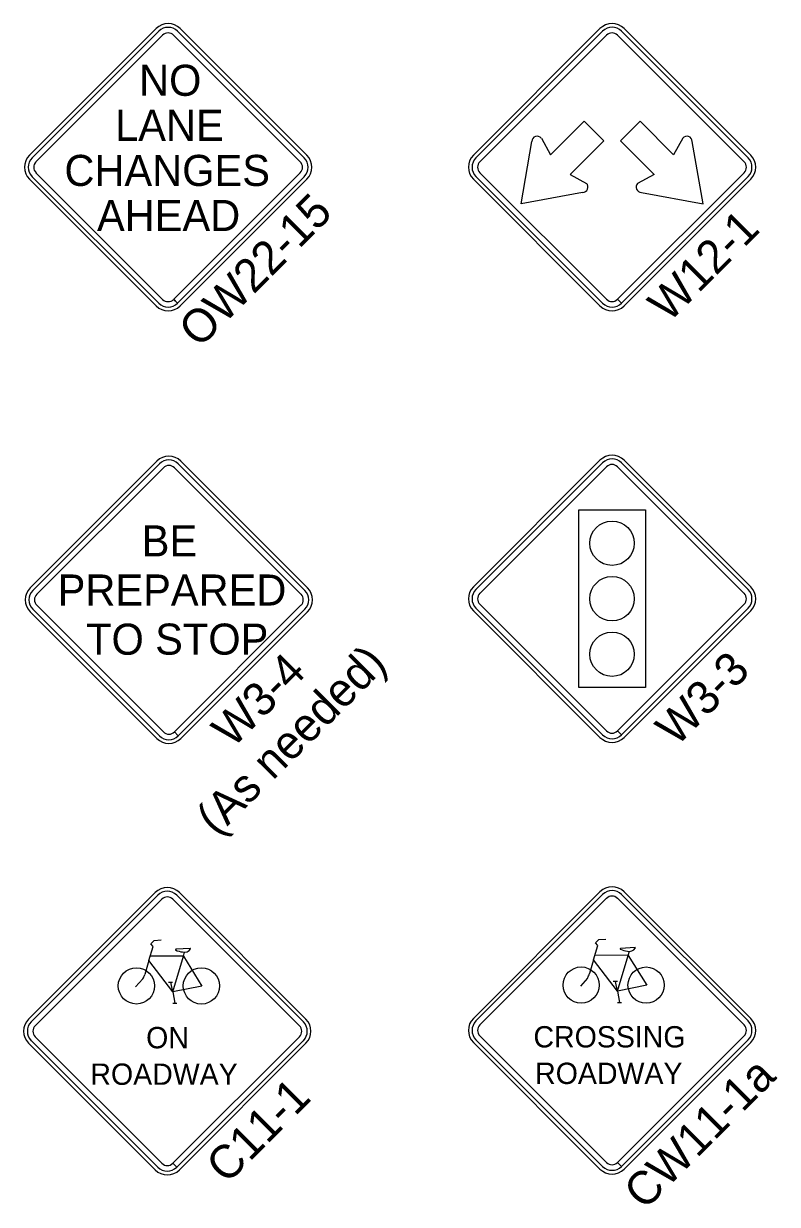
# Model space of a CAD drawing. Extents: x 1458 to 4498, y 17709 to 24109.
# Drawn here: x 3714 to 4053, y 22534 to 23066 of the extents above; entities that cross this region are included whole.
import ezdxf

# ---------------------------------------------------------------- set-up
doc = ezdxf.new("R2010")
doc.units = 0
doc.layers.add('P_TRAF_TCP_General', color=7, linetype='Continuous')

msp = doc.modelspace()

# ---------------------------------------------------------------- linework, layer by layer
at = {"layer": 'P_TRAF_TCP_General'}
for p, q in [((3773.42, 23063.84), (3716.41, 23006.84)), ((3774.6, 23062.66), (3717.6, 23005.65)), ((3840.09, 23005.65), (3783.09, 23062.66)), ((3841.27, 23006.84), (3784.27, 23063.84)), ((3973.24, 23063.86), (3916.24, 23006.85)), ((3974.43, 23062.67), (3917.42, 23005.67)), ((4039.91, 23005.67), (3982.91, 23062.67)), ((4041.1, 23006.85), (3984.09, 23063.86)), ((3719.36, 23003.89), (3776.37, 23060.89)), ((3781.32, 23060.89), (3838.32, 23003.89)), ((3919.19, 23003.9), (3976.19, 23060.9)), ((3981.14, 23060.9), (4038.15, 23003.9)), ((3950.95, 23006.99), (3966.07, 23022.12)), ((3966.07, 23022.13), (3974.9, 23013.29)), ((3991.27, 23022.13), (3982.43, 23013.29)), ((4006.39, 23006.99), (3991.26, 23022.12)), ((3946.84, 23014.48), (3950.95, 23006.99)), ((3974.9, 23013.3), (3959.77, 22998.17)), ((3982.44, 23013.3), (3997.56, 22998.17)), ((4010.5, 23014.48), (4006.39, 23006.99)), ((3937.71, 22984.93), (3942.58, 23013.03)), ((4019.62, 22984.93), (4014.76, 23013.03)), ((3776.37, 22941.93), (3719.36, 22998.94)), ((3838.32, 22998.94), (3781.34, 22941.95)), ((3976.19, 22941.95), (3919.19, 22998.95)), ((3976.19, 22941.95), (3919.19, 22998.95)), ((3959.77, 22998.17), (3967.14, 22994.16)), ((4038.15, 22998.95), (3981.16, 22941.96)), ((3997.56, 22998.17), (3990.2, 22994.16)), ((3716.41, 22995.99), (3773.42, 22938.98)), ((3717.6, 22997.17), (3774.6, 22940.17)), ((3783.1, 22940.18), (3840.09, 22997.17)), ((3784.27, 22938.98), (3841.27, 22995.99)), ((3916.24, 22996), (3973.24, 22939)), ((3917.42, 22997.18), (3974.43, 22940.18)), ((3917.42, 22997.18), (3974.43, 22940.18)), ((3982.93, 22940.2), (4039.91, 22997.18)), ((3984.09, 22939), (4041.1, 22996)), ((3965.44, 22990.12), (3937.71, 22984.93)), ((3991.89, 22990.12), (4019.62, 22984.93)), ((3783.09, 22940.17), (3781.32, 22941.93)), ((3783.09, 22940.17), (3781.32, 22941.93)), ((3781.34, 22941.95), (3783.1, 22940.18)), ((3781.34, 22941.95), (3783.1, 22940.18)), ((3982.91, 22940.18), (3981.14, 22941.95)), ((3982.91, 22940.18), (3981.14, 22941.95)), ((3981.16, 22941.96), (3982.93, 22940.2)), ((3773.75, 22869.06), (3716.74, 22812.06)), ((3774.93, 22867.88), (3717.93, 22810.87)), ((3774.93, 22867.88), (3717.93, 22810.87)), ((3774.93, 22867.88), (3717.93, 22810.87)), ((3719.69, 22809.11), (3776.7, 22866.11)), ((3719.69, 22809.11), (3776.7, 22866.11)), ((3781.65, 22866.11), (3838.65, 22809.11)), ((3781.65, 22866.11), (3838.65, 22809.11)), ((3840.42, 22810.87), (3783.41, 22867.88)), ((3840.42, 22810.87), (3783.41, 22867.88)), ((3840.42, 22810.87), (3783.41, 22867.88)), ((3841.6, 22812.06), (3784.6, 22869.06)), ((3973.24, 22869.5), (3916.24, 22812.5)), ((3974.43, 22868.32), (3917.42, 22811.31)), ((3919.19, 22809.54), (3976.19, 22866.55)), ((3981.14, 22866.55), (4038.15, 22809.54)), ((4039.91, 22811.31), (3982.91, 22868.32)), ((4041.1, 22812.5), (3984.09, 22869.5)), ((3716.74, 22801.21), (3773.75, 22744.2)), ((3717.93, 22802.39), (3774.93, 22745.39)), ((3717.93, 22802.39), (3774.93, 22745.39)), ((3717.93, 22802.39), (3774.93, 22745.39)), ((3776.7, 22747.15), (3719.69, 22804.16)), ((3776.7, 22747.15), (3719.69, 22804.16)), ((3838.65, 22804.16), (3781.66, 22747.17)), ((3838.65, 22804.16), (3781.66, 22747.17)), ((3783.41, 22745.39), (3840.42, 22802.39)), ((3783.43, 22745.4), (3840.42, 22802.39)), ((3783.43, 22745.4), (3840.42, 22802.39)), ((3784.6, 22744.2), (3841.6, 22801.21)), ((3916.24, 22801.65), (3973.24, 22744.64)), ((3917.42, 22802.83), (3974.43, 22745.82)), ((3976.19, 22747.59), (3919.19, 22804.6)), ((4038.15, 22804.6), (3981.16, 22747.61)), ((3982.93, 22745.84), (4039.91, 22802.83)), ((3984.09, 22744.64), (4041.1, 22801.65)), ((3982.91, 22745.82), (3981.14, 22747.59)), ((3982.91, 22745.82), (3981.14, 22747.59)), ((3981.16, 22747.61), (3982.93, 22745.84)), ((3981.16, 22747.61), (3982.93, 22745.84)), ((3783.41, 22745.39), (3781.65, 22747.15)), ((3783.41, 22745.39), (3781.65, 22747.15)), ((3781.66, 22747.17), (3783.43, 22745.4)), ((3781.66, 22747.17), (3783.43, 22745.4)), ((3773.04, 22674.77), (3716.04, 22617.77)), ((3774.23, 22673.59), (3717.22, 22616.58)), ((3839.71, 22616.58), (3782.71, 22673.59)), ((3840.9, 22617.77), (3783.89, 22674.77)), ((3973.24, 22675.15), (3916.24, 22618.14)), ((3974.43, 22673.96), (3917.42, 22616.96)), ((4039.91, 22616.96), (3982.91, 22673.96)), ((4041.1, 22618.14), (3984.09, 22675.15)), ((3718.99, 22614.81), (3775.99, 22671.82)), ((3780.94, 22671.82), (3837.95, 22614.81)), ((3919.19, 22615.19), (3976.19, 22672.2)), ((3981.14, 22672.2), (4038.15, 22615.19)), ((3771.06, 22651.77), (3772.49, 22653.25)), ((3771.06, 22651.77), (3772.49, 22653.25)), ((3772.08, 22650.55), (3771.06, 22651.77)), ((3772.08, 22650.55), (3771.06, 22651.77)), ((3772.49, 22653.25), (3775.72, 22653.45)), ((3772.49, 22653.25), (3775.72, 22653.45)), ((3971.26, 22652.15), (3972.69, 22653.63)), ((3971.26, 22652.15), (3972.69, 22653.63)), ((3972.28, 22650.93), (3971.26, 22652.15)), ((3972.28, 22650.93), (3971.26, 22652.15)), ((3972.69, 22653.63), (3975.92, 22653.83)), ((3972.69, 22653.63), (3975.92, 22653.83)), ((3770.1, 22644.15), (3772.08, 22650.55)), ((3770.1, 22644.15), (3772.08, 22650.55)), ((3788.84, 22649.62), (3782.28, 22649.25)), ((3788.84, 22649.62), (3782.28, 22649.25)), ((3785.76, 22646.08), (3786.26, 22647.98)), ((3785.76, 22646.08), (3786.26, 22647.98)), ((3970.3, 22644.53), (3972.28, 22650.93)), ((3970.3, 22644.53), (3972.28, 22650.93)), ((3985.96, 22646.45), (3970.89, 22646.53)), ((3981.09, 22630.43), (3985.96, 22646.45)), ((3981.09, 22630.43), (3985.96, 22646.45)), ((3989.04, 22650), (3982.48, 22649.62)), ((3989.04, 22650), (3982.48, 22649.62)), ((3985.96, 22646.45), (3986.46, 22648.35)), ((3985.96, 22646.45), (3986.46, 22648.35)), ((3985.96, 22646.45), (3994.28, 22633.05)), ((3985.96, 22646.45), (3994.28, 22633.05)), ((3770.1, 22644.15), (3768.37, 22637.94)), ((3770.1, 22644.15), (3768.37, 22637.94)), ((3780.89, 22630.06), (3770.1, 22644.15)), ((3780.89, 22630.06), (3770.1, 22644.15)), ((3785.76, 22646.08), (3770.69, 22646.15)), ((3780.89, 22630.06), (3785.76, 22646.08)), ((3780.89, 22630.06), (3785.76, 22646.08)), ((3785.76, 22646.08), (3794.08, 22632.68)), ((3785.76, 22646.08), (3794.08, 22632.68)), ((3970.3, 22644.53), (3968.57, 22638.31)), ((3970.3, 22644.53), (3968.57, 22638.31)), ((3981.09, 22630.43), (3970.3, 22644.53)), ((3981.09, 22630.43), (3970.3, 22644.53)), ((3767.46, 22635.89), (3764.2, 22632.33)), ((3767.46, 22635.89), (3764.2, 22632.33)), ((3967.66, 22636.27), (3964.4, 22632.71)), ((3967.66, 22636.27), (3964.4, 22632.71)), ((3779, 22634.49), (3780.88, 22634.49)), ((3779, 22634.49), (3780.88, 22634.49)), ((3780.89, 22630.06), (3780.03, 22634.42)), ((3794.08, 22632.68), (3780.89, 22630.06)), ((3794.08, 22632.68), (3780.89, 22630.06)), ((3979.2, 22634.87), (3981.08, 22634.87)), ((3979.2, 22634.87), (3981.08, 22634.87)), ((3981.09, 22630.43), (3980.23, 22634.8)), ((3994.28, 22633.05), (3981.09, 22630.43)), ((3994.28, 22633.05), (3981.09, 22630.43)), ((3780.89, 22630.06), (3781.86, 22624.92)), ((3780.89, 22630.06), (3781.86, 22624.92)), ((3981.09, 22630.43), (3982.07, 22625.29)), ((3981.09, 22630.43), (3982.07, 22625.29)), ((3981.12, 22625.33), (3982.99, 22625.33)), ((3981.12, 22625.33), (3982.99, 22625.33)), ((3780.92, 22624.96), (3782.79, 22624.96)), ((3780.92, 22624.96), (3782.79, 22624.96)), ((3775.99, 22552.86), (3718.99, 22609.87)), ((3837.95, 22609.87), (3780.96, 22552.88)), ((3976.19, 22553.24), (3919.19, 22610.24)), ((4038.15, 22610.24), (3981.16, 22553.25)), ((3716.04, 22606.92), (3773.04, 22549.91)), ((3717.22, 22608.1), (3774.23, 22551.09)), ((3782.73, 22551.11), (3839.71, 22608.1)), ((3783.89, 22549.91), (3840.9, 22606.92)), ((3916.24, 22607.29), (3973.24, 22550.29)), ((3917.42, 22608.48), (3974.43, 22551.47)), ((3982.93, 22551.49), (4039.91, 22608.48)), ((3984.09, 22550.29), (4041.1, 22607.29)), ((3782.71, 22551.09), (3780.94, 22552.86)), ((3782.71, 22551.09), (3780.94, 22552.86)), ((3780.96, 22552.88), (3782.73, 22551.11)), ((3780.96, 22552.88), (3782.73, 22551.11)), ((3982.91, 22551.47), (3981.14, 22553.24)), ((3982.91, 22551.47), (3981.14, 22553.24)), ((3981.16, 22553.25), (3982.93, 22551.49)), ((3981.16, 22553.25), (3982.93, 22551.49))]:
    msp.add_line(p, q, dxfattribs=at)
msp.add_lwpolyline([(3963.68, 22847.1), (3993.67, 22847.1), (3993.67, 22767.13), (3963.68, 22767.13)], close=True, dxfattribs=at)
for centre, radius in [((3978.68, 22832.11), 10), ((3978.68, 22807.12), 10), ((3978.68, 22782.13), 10), ((3964.76, 22633.14), 8.16), ((3994.01, 22633.12), 8.16), ((3764.56, 22632.76), 8.16), ((3793.81, 22632.75), 8.16)]:
    msp.add_circle(centre, radius, dxfattribs=at)
for centre, radius, start, end in [((3778.84, 23058.42), 7.67, 45, 135), ((3778.84, 23058.42), 6, 45, 135), ((3778.84, 23058.42), 3.5, 45, 135), ((3978.67, 23058.43), 7.67, 45, 135), ((3978.67, 23058.43), 6, 45, 135), ((3978.67, 23058.43), 3.5, 45, 135), ((3944.95, 23013.03), 2.38, 37.6899, 180), ((4012.38, 23013.03), 2.38, 360, 142.3101), ((3721.84, 23001.41), 7.67, 135, 225), ((3721.84, 23001.41), 6, 135, 225), ((3721.84, 23001.41), 3.5, 135, 225), ((3835.85, 23001.41), 3.5, 315, 45), ((3835.85, 23001.41), 6, 315, 45), ((3835.85, 23001.41), 7.67, 315, 45), ((3921.66, 23001.43), 7.67, 135, 225), ((3921.66, 23001.43), 6, 135, 225), ((3921.66, 23001.43), 3.5, 135, 225), ((4035.67, 23001.43), 3.5, 315, 45), ((4035.67, 23001.43), 6, 315, 45), ((4035.67, 23001.43), 7.67, 315, 45), ((3965.44, 22992.5), 2.38, 270, 44.5046), ((3991.89, 22992.5), 2.38, 135.4954, 270), ((3778.84, 22944.41), 7.67, 225, 315), ((3778.84, 22944.41), 6, 225, 315), ((3778.84, 22944.41), 3.5, 225, 315), ((3978.67, 22944.42), 7.67, 225, 315), ((3978.67, 22944.42), 6, 225, 315), ((3978.67, 22944.42), 3.5, 225, 315), ((3779.17, 22863.64), 7.67, 45, 135), ((3978.67, 22864.08), 7.67, 45, 135), ((3978.67, 22864.08), 6, 45, 135), ((3779.17, 22863.64), 6, 45, 135), ((3779.17, 22863.64), 6, 45, 135), ((3779.17, 22863.64), 6, 45, 135), ((3779.17, 22863.64), 3.5, 45, 135), ((3779.17, 22863.64), 3.5, 45, 135), ((3978.67, 22864.08), 3.5, 45, 135), ((3722.17, 22806.63), 7.67, 135, 225), ((3836.18, 22806.63), 7.67, 315, 45), ((3921.66, 22807.07), 7.67, 135, 225), ((3921.66, 22807.07), 6, 135, 225), ((4035.67, 22807.07), 6, 315, 45), ((4035.67, 22807.07), 7.67, 315, 45), ((3722.17, 22806.63), 6, 135, 225), ((3722.17, 22806.63), 6, 135, 225), ((3722.17, 22806.63), 6, 135, 225), ((3722.17, 22806.63), 3.5, 135, 225), ((3722.17, 22806.63), 3.5, 135, 225), ((3836.18, 22806.63), 3.5, 315, 45), ((3836.18, 22806.63), 3.5, 315, 45), ((3836.18, 22806.63), 6, 315, 45), ((3836.18, 22806.63), 6, 315, 45), ((3836.18, 22806.63), 6, 315, 45), ((3921.66, 22807.07), 3.5, 135, 225), ((4035.67, 22807.07), 3.5, 315, 45), ((3978.67, 22750.07), 3.5, 225, 315), ((3779.17, 22749.63), 7.67, 225, 315), ((3779.17, 22749.63), 6, 225, 315), ((3779.17, 22749.63), 6, 225, 315), ((3779.17, 22749.63), 6, 225, 315), ((3779.17, 22749.63), 3.5, 225, 315), ((3779.17, 22749.63), 3.5, 225, 315), ((3978.67, 22750.07), 7.67, 225, 315), ((3978.67, 22750.07), 6, 225, 315), ((3778.47, 22669.35), 7.67, 45, 135), ((3778.47, 22669.35), 6, 45, 135), ((3978.67, 22669.72), 7.67, 45, 135), ((3978.67, 22669.72), 6, 45, 135), ((3978.67, 22669.72), 3.5, 45, 135), ((3778.47, 22669.35), 3.5, 45, 135), ((3782.37, 22649.05), 0.191, 98.1714, 240.5811), ((3782.37, 22649.05), 0.191, 98.1714, 240.5811), ((3787.07, 22659.95), 12.04, 246.229, 261.8057), ((3787.07, 22659.95), 12.04, 246.229, 261.8057), ((3786.15, 22651.35), 3.41, 256.4886, 325.1285), ((3786.15, 22651.35), 3.41, 256.4886, 325.1285), ((3788.79, 22649.45), 0.166, 336.8194, 78.5167), ((3788.79, 22649.45), 0.166, 336.8194, 78.5167), ((3982.57, 22649.43), 0.191, 98.1714, 240.5811), ((3982.57, 22649.43), 0.191, 98.1714, 240.5811), ((3987.27, 22660.32), 12.04, 246.229, 261.8057), ((3987.27, 22660.32), 12.04, 246.229, 261.8057), ((3986.35, 22651.73), 3.41, 256.4886, 325.1285), ((3986.35, 22651.73), 3.41, 256.4886, 325.1285), ((3988.99, 22649.83), 0.166, 336.8194, 78.5167), ((3988.99, 22649.83), 0.166, 336.8194, 78.5167), ((3727.62, 22654.96), 44.17, 334.4184, 337.3217), ((3727.62, 22654.96), 44.17, 334.4184, 337.3217), ((3927.82, 22655.34), 44.17, 334.4184, 337.3217), ((3927.82, 22655.34), 44.17, 334.4184, 337.3217), ((3721.46, 22612.34), 7.67, 135, 225), ((3721.46, 22612.34), 6, 135, 225), ((3721.46, 22612.34), 3.5, 135, 225), ((3835.47, 22612.34), 3.5, 315, 45), ((3835.47, 22612.34), 6, 315, 45), ((3835.47, 22612.34), 7.67, 315, 45), ((3921.66, 22612.72), 7.67, 135, 225), ((3921.66, 22612.72), 6, 135, 225), ((3921.66, 22612.72), 3.5, 135, 225), ((4035.67, 22612.72), 3.5, 315, 45), ((4035.67, 22612.72), 6, 315, 45), ((4035.67, 22612.72), 7.67, 315, 45), ((3778.47, 22555.34), 6, 225, 315), ((3778.47, 22555.34), 3.5, 225, 315), ((3978.67, 22555.71), 6, 225, 315), ((3978.67, 22555.71), 3.5, 225, 315), ((3778.47, 22555.34), 7.67, 225, 315), ((3978.67, 22555.71), 7.67, 225, 315)]:
    msp.add_arc(centre, radius, start, end, dxfattribs=at)

# ---------------------------------------------------------------- texts
for s, height, p in [('NO', 13.994, (3765.76, 23033.59)), ('LANE', 13.994, (3754.97, 23013.29)), ('CHANGES', 13.994, (3732.15, 22993)), ('AHEAD', 13.994, (3746.82, 22972.71)), ('BE', 13.994, (3766.95, 22826.15)), ('PREPARED', 13.994, (3729.11, 22804.04)), ('TO ', 13.994, (3741.92, 22781.9)), ('       STOP', 13.9944, (3736.61, 22781.93)), ('CROSSING', 9.6, (3943.29, 22605.04)), ('ON', 9.6, (3768.93, 22604.67)), ('ROADWAY', 9.6, (3743.84, 22588.21)), ('ROADWAY', 9.6, (3944.04, 22588.59))]:
    msp.add_text(s, height=height, dxfattribs=at).set_placement(p)
for s, p in [('OW22-15', (3792.87, 22919.56)), ('W12-1', (4004.18, 22931.06)), ('(As needed)', (3800.72, 22699.79)), ('W3-4', (3807.82, 22739.4)), ('W3-3', (4007.61, 22740.14)), ('CW11-1a', (3993.26, 22531.34)), ('C11-1', (3805.22, 22543.13))]:
    msp.add_text(s, height=14.994, rotation=45, dxfattribs=at).set_placement(p)

doc.saveas('drawing.dxf')
